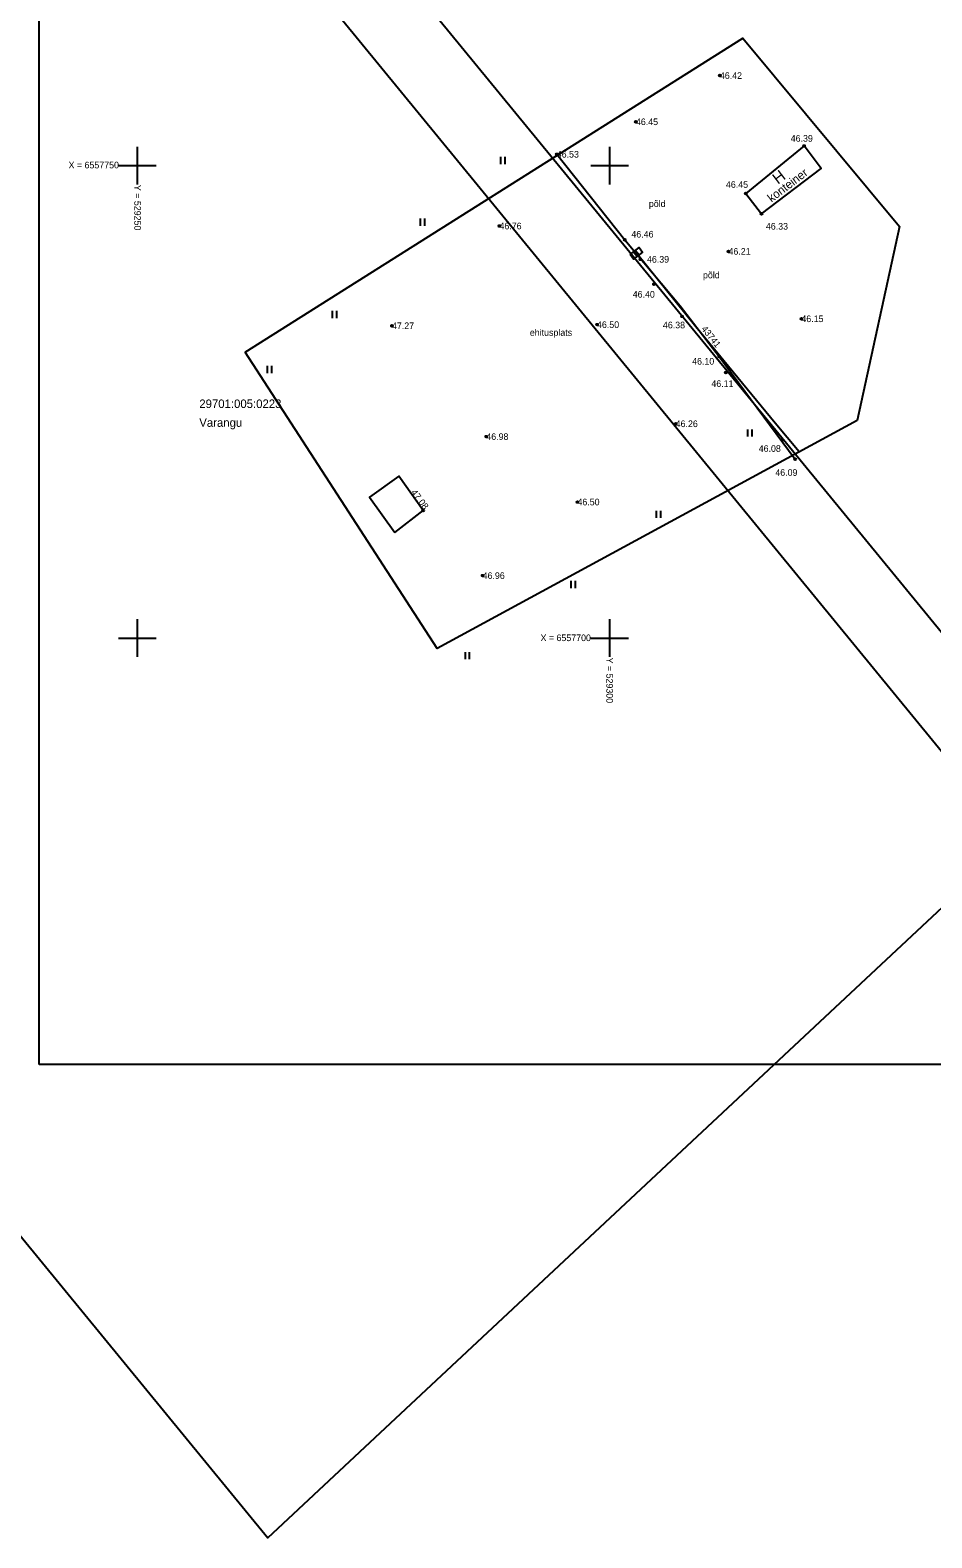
# Model space of a CAD drawing. Extents: x 529142 to 529430, y 6557605 to 6557874.
# Drawn here: x 529238.7 to 529334.1, y 6557604.8 to 6557764.3 of the extents above; entities that cross this region are included whole.
import ezdxf

# ---------------------------------------------------------------- set-up
doc = ezdxf.new("R2010")
doc.units = 0
for name, color, linetype in [('ELRAJATISMP', 7, 'Continuous'), ('HALJASTUS', 7, 'Continuous'), ('HOONE', 7, 'Continuous'), ('HOONEDET', 7, 'Continuous'), ('KORGUS', 7, 'Continuous'), ('MOOTPIIR', 7, 'Continuous'), ('MPKAABEL', 7, 'Continuous'), ('PIIR', 7, 'Continuous'), ('VORK', 7, 'Continuous'), ('VORMISTUS', 7, 'Continuous')]:
    doc.layers.add(name, color=color, linetype=linetype)

msp = doc.modelspace()

# ---------------------------------------------------------------- linework, layer by layer
at = {"layer": 'ELRAJATISMP'}
for p, q in [((529302.55, 6557740.87), (529302.92, 6557740.4)), ((529302.76, 6557741.03), (529303.13, 6557740.56))]:
    msp.add_line(p, q, dxfattribs=at)
msp.add_lwpolyline([(529302.18, 6557740.58), (529303.12, 6557741.32), (529303.49, 6557740.85), (529302.55, 6557740.11)], close=True, dxfattribs=at)
at = {"layer": 'HALJASTUS'}
for p, q in [((529288.46, 6557750.93), (529288.46, 6557750.17)), ((529288.91, 6557750.93), (529288.91, 6557750.17)), ((529279.95, 6557744.39), (529279.95, 6557743.63)), ((529280.41, 6557744.39), (529280.41, 6557743.63)), ((529270.64, 6557734.63), (529270.64, 6557733.86)), ((529271.1, 6557734.63), (529271.1, 6557733.86)), ((529263.75, 6557728.8), (529263.75, 6557728.04)), ((529264.2, 6557728.8), (529264.2, 6557728.04)), ((529314.6, 6557722.08), (529314.6, 6557721.32)), ((529315.06, 6557722.08), (529315.06, 6557721.32)), ((529304.93, 6557713.48), (529304.93, 6557712.72)), ((529305.39, 6557713.48), (529305.39, 6557712.72)), ((529295.89, 6557706.05), (529295.89, 6557705.28)), ((529296.35, 6557706.05), (529296.35, 6557705.28)), ((529284.7, 6557698.52), (529284.7, 6557697.76)), ((529285.15, 6557698.52), (529285.15, 6557697.76))]:
    msp.add_line(p, q, dxfattribs=at)
msp.add_lwpolyline([(529294.41, 6557751.2), (529301.61, 6557742.15), (529307.46, 6557735.15), (529311.62, 6557729.81), (529319.65, 6557718.94)], dxfattribs=at)
at = {"layer": 'HOONEDET'}
for points in [[(529320.59, 6557752.08), (529314.43, 6557747.05), (529316.08, 6557744.89), (529322.4, 6557749.7), (529320.59, 6557752.08)], [(529277.25, 6557711.16), (529280.26, 6557713.49), (529277.67, 6557717.14), (529274.57, 6557714.93), (529277.25, 6557711.16)]]:
    msp.add_lwpolyline(points, dxfattribs=at)
at = {"layer": 'KORGUS'}
for centre in [(529311.68, 6557759.53), (529302.79, 6557754.64), (529294.41, 6557751.2), (529320.59, 6557752.08), (529314.43, 6557747.05), (529316.08, 6557744.89), (529288.34, 6557743.61), (529301.61, 6557742.15), (529303.26, 6557740.08), (529312.59, 6557740.92), (529304.7, 6557737.44), (529307.67, 6557734.05), (529320.31, 6557733.79), (529276.96, 6557733.05), (529298.67, 6557733.17), (529311.62, 6557729.81), (529312.31, 6557728.11), (529307, 6557722.68), (529286.95, 6557721.32), (529318.28, 6557720.97), (529319.64, 6557718.94), (529296.6, 6557714.4), (529280.26, 6557713.49), (529286.56, 6557706.61)]:
    msp.add_circle(centre, 0.1, dxfattribs=at)
at = {"layer": 'MOOTPIIR'}
msp.add_lwpolyline([(529261.4, 6557730.27), (529314.1, 6557763.5), (529330.71, 6557743.56), (529326.23, 6557723.04), (529281.76, 6557698.91)], close=True, dxfattribs=at)
at = {"layer": 'MPKAABEL'}
msp.add_lwpolyline([(529320.09, 6557719.71), (529317.52, 6557722.73), (529309.12, 6557732.93), (529302.84, 6557740.72)], dxfattribs=at)
at = {"layer": 'PIIR'}
for points in [[(529240.36, 6557816.2), (529348.66, 6557684.15), (529355.79, 6557690.82), (529382.39, 6557716.11), (529429.5, 6557754.74), (529425.44, 6557759.68), (529331.39, 6557873.99)], [(529141.76, 6557753.61), (529263.81, 6557604.78), (529342.84, 6557678.62), (529233.56, 6557811.89)]]:
    msp.add_lwpolyline(points, close=True, dxfattribs=at)
at = {"layer": 'VORK'}
for p, q in [((529250, 6557752), (529250, 6557748)), ((529300, 6557752), (529300, 6557748)), ((529248, 6557750), (529252, 6557750)), ((529298, 6557750), (529302, 6557750)), ((529250, 6557702), (529250, 6557698)), ((529300, 6557702), (529300, 6557698)), ((529248, 6557700), (529252, 6557700)), ((529298, 6557700), (529302, 6557700))]:
    msp.add_line(p, q, dxfattribs=at)
at = {"layer": 'VORMISTUS'}
msp.add_lwpolyline([(529239.6, 6557654.86), (529239.6, 6557793.36), (529429.6, 6557793.36), (529429.6, 6557654.86)], close=True, dxfattribs=at)

# ---------------------------------------------------------------- texts
at = {"layer": 'HALJASTUS'}
for s, p in [('põld', (529304.16, 6557745.62)), ('põld', (529309.89, 6557738.07)), ('ehitusplats', (529291.56, 6557731.99))]:
    msp.add_text(s, height=0.7, dxfattribs=at).set_placement(p)
at = {"layer": 'HOONE'}
for s, height, p in [('konteiner', 0.9, (529317.14, 6557746.08)), ('H', 1.2, (529317.82, 6557747.97))]:
    msp.add_text(s, height=height, rotation=37.1761, dxfattribs=at).set_placement(p)
at = {"layer": 'KORGUS'}
for s, p in [('46.42', (529311.68, 6557759.18)), ('46.45', (529302.79, 6557754.29)), ('46.39', (529319.18, 6557752.53)), ('46.53', (529294.41, 6557750.85)), ('46.45', (529312.32, 6557747.65)), ('46.76', (529288.34, 6557743.26)), ('46.46', (529302.31, 6557742.39)), ('46.33', (529316.55, 6557743.23)), ('46.39', (529303.96, 6557739.73)), ('46.21', (529312.59, 6557740.57)), ('46.40', (529302.45, 6557736.03)), ('46.50', (529298.67, 6557732.82)), ('46.15', (529320.31, 6557733.44)), ('47.27', (529276.96, 6557732.7)), ('46.38', (529305.65, 6557732.78)), ('46.10', (529308.74, 6557728.94)), ('46.11', (529310.78, 6557726.58)), ('46.26', (529307, 6557722.33)), ('46.98', (529286.95, 6557720.97)), ('46.08', (529315.79, 6557719.71)), ('46.09', (529317.55, 6557717.17)), ('46.50', (529296.6, 6557714.05)), ('46.96', (529286.56, 6557706.26))]:
    msp.add_text(s, height=0.7, dxfattribs=at).set_placement(p)
msp.add_text('47.08', height=0.7, rotation=306.9401, dxfattribs=at).set_placement((529278.93, 6557715.41))
at = {"layer": 'MPKAABEL'}
msp.add_text('43741', height=0.7, rotation=308.5906, dxfattribs=at).set_placement((529309.67, 6557732.7))
at = {"layer": 'PIIR'}
for s, p in [('29701:005:0223', (529256.56, 6557724.35)), ('Varangu ', (529256.56, 6557722.36))]:
    msp.add_text(s, height=0.9, dxfattribs=at).set_placement(p)
at = {"layer": 'VORK'}
for s, p in [('X = 6557750', (529242.72, 6557749.71)), ('X = 6557700', (529292.69, 6557699.68))]:
    msp.add_text(s, height=0.7, dxfattribs=at).set_placement(p)
for s, p in [('Y = 529250 ', (529249.68, 6557747.96)), ('Y = 529300 ', (529299.66, 6557697.93))]:
    msp.add_text(s, height=0.7, rotation=270, dxfattribs=at).set_placement(p)

doc.saveas('drawing.dxf')
